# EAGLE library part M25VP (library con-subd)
SUB-D
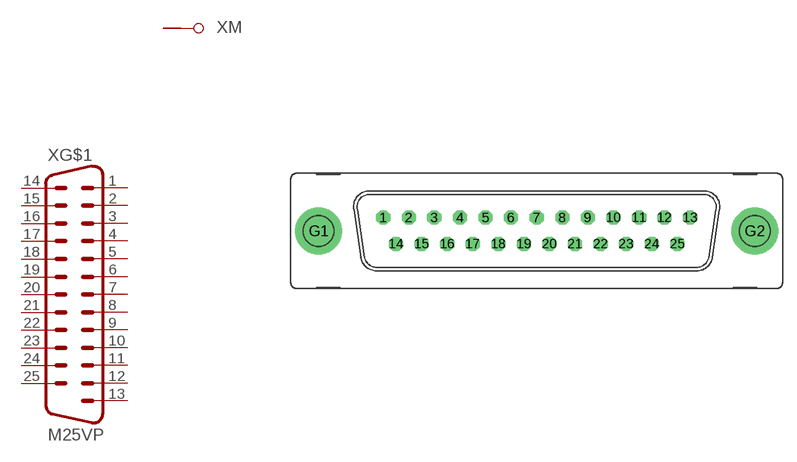
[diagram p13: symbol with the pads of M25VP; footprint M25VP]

Designator prefix X; gates G$1=M25 M=GND

## M25VP (OC_FARNELL: unknown; OC_NEWARK: unknown)  [M25VP]
1  G$1:1  pas
2  G$1:2  pas
3  G$1:3  pas
4  G$1:4  pas
5  G$1:5  pas
6  G$1:6  pas
7  G$1:7  pas
8  G$1:8  pas
9  G$1:9  pas
10  G$1:10  pas
11  G$1:11  pas
12  G$1:12  pas
13  G$1:13  pas
14  G$1:14  pas
15  G$1:15  pas
16  G$1:16  pas
17  G$1:17  pas
18  G$1:18  pas
19  G$1:19  pas
20  G$1:20  pas
21  G$1:21  pas
22  G$1:22  pas
23  G$1:23  pas
24  G$1:24  pas
25  G$1:25  pas
G1  M:G1  pas
G2  M:G2  pas

## Footprint M25VP (pad centres in mm)
SUB-D
drill 1.016 octagon: 1 -16.561,1.422; 2 -13.792,1.422; 3 -11.049,1.422; 4 -8.28,1.422; 5 -5.512,1.422; 6 -2.769,1.422; 7 0,1.422; 8 2.769,1.422; 9 5.512,1.422; 10 8.28,1.422; 11 11.049,1.422; 12 13.792,1.422; 13 16.561,1.422; 14 -15.189,-1.422; 15 -12.421,-1.422; 16 -9.652,-1.422; 17 -6.909,-1.422; 18 -4.14,-1.422; 19 -1.372,-1.422; 20 1.372,-1.422; 21 4.14,-1.422; 22 6.909,-1.422; 23 9.652,-1.422; 24 12.421,-1.422; 25 15.189,-1.422
drill 3.302 pad 5.08 round: G1 -23.52,0; G2 23.52,0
